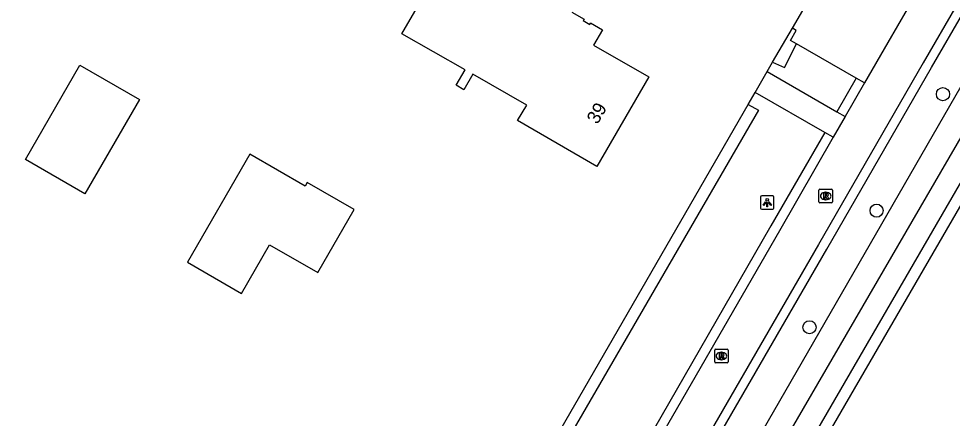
# Model space of a CAD drawing. Extents: x 156502 to 159074, y 384229 to 386094.
# Drawn here: x 157237.7 to 157307.2, y 385687.2 to 385716.9 of the extents above; entities that cross this region are included whole.
import ezdxf

# ---------------------------------------------------------------- set-up
doc = ezdxf.new("R2010")
doc.units = 0
for name, color, linetype in [('IMGEO_Boom', 7, 'Continuous'), ('IMGEO_Gemengd_bos', 7, 'Continuous'), ('IMGEO_Greppel_droge_sloot', 7, 'Continuous'), ('IMGEO_Groenvoorziening', 7, 'Continuous'), ('IMGEO_Hek', 7, 'Continuous'), ('IMGEO_Lichtpunt', 7, 'Continuous'), ('IMGEO_Pand', 7, 'Continuous'), ('IMGEO_Pand_nummerreeks', 7, 'Continuous'), ('IMGEO_Rijbaan_lokaal_halfverhard', 7, 'Continuous'), ('IMGEO_Rijbaan_lokaal_open', 7, 'Continuous'), ('IMGEO_Rioolput', 7, 'Continuous'), ('IMGEO_Voetpad_open', 7, 'Continuous')]:
    doc.layers.add(name, color=color, linetype=linetype)

msp = doc.modelspace()

# ---------------------------------------------------------------- linework, layer by layer
at = {"layer": 'IMGEO_Boom'}
for centre in [(157306.454, 385711.295), (157301.516, 385702.617), (157296.521, 385693.933)]:
    msp.add_circle(centre, 0.489, dxfattribs=at)
at = {"layer": 'IMGEO_Gemengd_bos'}
msp.add_lwpolyline([(157395.472, 385857.325), (157372.587, 385816.736), (157334.959, 385750), (157287.88, 385668.677), (157271.388, 385640.19), (157191.031, 385500), (157152.554, 385432.884), (157150.665, 385429.588), (157146.166, 385421.741)], dxfattribs=at)
at = {"layer": 'IMGEO_Greppel_droge_sloot'}
for points in [[(157393.364, 385858.054), (157393.108, 385857.612), (157362.753, 385804.111), (157325.818, 385739.168), (157293.922, 385684.217), (157277.506, 385655.557), (157259.264, 385623.708), (157238.621, 385587.751), (157224.85, 385563.789), (157203.074, 385525.899), (157174.272, 385475.365), (157161.248, 385452.051), (157151.078, 385433.934), (157146.7, 385427.265), (157144.863, 385424.97)], [(157146.463, 385424.365), (157148.979, 385428.052), (157150.577, 385430.986), (157151.892, 385433.401), (157190.309, 385500.414), (157270.667, 385640.605), (157287.16, 385669.094), (157334.237, 385750.413), (157371.862, 385817.145), (157394.598, 385857.47)]]:
    msp.add_lwpolyline(points, dxfattribs=at)
at = {"layer": 'IMGEO_Groenvoorziening'}
for points in [[(157284.199, 385670.89), (157329.731, 385750), (157392.248, 385858.973)], [(157293.777, 385713.687), (157295.26, 385716.199)], [(157293.777, 385713.687), (157294.665, 385713.269), (157295.56, 385715.032)], [(157293.366, 385712.992), (157293.777, 385713.687)], [(157291.965, 385710.53), (157292.478, 385711.419)], [(157268.668, 385670.142), (157291.965, 385710.53)], [(157291.965, 385710.53), (157292.73, 385710.099), (157269.35, 385669.721)]]:
    msp.add_lwpolyline(points, dxfattribs=at)
at = {"layer": 'IMGEO_Hek'}
msp.add_lwpolyline([(157334.959, 385750), (157287.88, 385668.677)], dxfattribs=at)
at = {"layer": 'IMGEO_Lichtpunt'}
for p, q in [((157292.887, 385703.62), (157292.887, 385702.813)), ((157292.887, 385703.62), (157292.887, 385702.813)), ((157293.789, 385703.715), (157292.981, 385703.715)), ((157293.789, 385703.715), (157292.981, 385703.715)), ((157293.883, 385702.813), (157293.883, 385703.62)), ((157293.883, 385702.813), (157293.883, 385703.62)), ((157292.981, 385702.719), (157293.789, 385702.719)), ((157292.981, 385702.719), (157293.789, 385702.719))]:
    msp.add_line(p, q, dxfattribs=at)
for points in [[(157293.261, 385703.284), (157293.3, 385703.256), (157293.112, 385702.994), (157293.074, 385703.021), (157293.261, 385703.284)], [(157293.363, 385703.236), (157293.41, 385703.236), (157293.41, 385702.914), (157293.363, 385702.914), (157293.363, 385703.236)], [(157293.473, 385703.256), (157293.511, 385703.283), (157293.698, 385703.021), (157293.659, 385702.993), (157293.473, 385703.256)]]:
    msp.add_lwpolyline(points, dxfattribs=at)
msp.add_circle((157293.386, 385703.418), 0.0994, dxfattribs=at)
for centre, start, end in [((157292.981, 385703.62), 90, 180), ((157292.981, 385703.62), 90, 180), ((157293.789, 385703.62), 0, 90), ((157293.789, 385703.62), 0, 90), ((157292.981, 385702.813), 180, 270), ((157292.981, 385702.813), 180, 270), ((157293.789, 385702.813), 270, 0), ((157293.789, 385702.813), 270, 360)]:
    msp.add_arc(centre, 0.0946, start, end, dxfattribs=at)
at = {"layer": 'IMGEO_Pand'}
for points in [[(157278.85, 385717.389), (157279.752, 385716.872), (157279.692, 385716.768), (157280.178, 385716.489), (157280.238, 385716.593), (157281.114, 385716.09), (157280.456, 385714.943), (157284.563, 385712.589), (157280.699, 385705.903), (157274.807, 385709.332), (157275.49, 385710.481), (157271.474, 385712.78), (157270.8, 385711.626), (157270.235, 385711.956), (157270.897, 385713.095), (157266.202, 385715.791), (157267.329, 385717.754)], [(157242.25, 385713.459), (157246.67, 385710.905), (157242.608, 385703.874), (157238.187, 385706.428), (157242.25, 385713.459)], [(157259.94, 385698.001), (157262.648, 385702.694), (157259.152, 385704.71), (157259.002, 385704.451), (157254.891, 385706.823), (157250.249, 385698.779), (157254.274, 385696.456), (157256.358, 385700.067), (157259.94, 385698.001)]]:
    msp.add_lwpolyline(points, dxfattribs=at)
at = {"layer": 'IMGEO_Rijbaan_lokaal_halfverhard'}
for points in [[(157281.966, 385672.234), (157287.901, 385682.571), (157297.811, 385699.744), (157305.606, 385713.266), (157310.603, 385721.93), (157349.521, 385789.087)], [(157299.987, 385712.485), (157298.547, 385709.98)], [(157298.547, 385709.98), (157299.169, 385709.618)], [(157297.663, 385708.443), (157293.657, 385701.479), (157284.326, 385685.265), (157273.57, 385666.582), (157272.301, 385664.385)], [(157298.287, 385708.085), (157297.663, 385708.443)]]:
    msp.add_lwpolyline(points, dxfattribs=at)
at = {"layer": 'IMGEO_Rijbaan_lokaal_open'}
for points in [[(157348.91, 385789.439), (157309.98, 385722.29), (157304.982, 385713.626), (157297.187, 385700.104), (157287.277, 385682.931), (157276.979, 385664.993), (157272.994, 385658.151), (157259.699, 385634.92)], [(157295.26, 385716.199), (157297.594, 385720.232)], [(157303.781, 385717.632), (157302.348, 385715.145), (157300.611, 385712.126)], [(157295.56, 385715.032), (157295.119, 385715.286), (157295.542, 385716.032), (157295.26, 385716.199)], [(157299.987, 385712.485), (157295.56, 385715.032)], [(157300.611, 385712.126), (157299.169, 385709.618)], [(157300.611, 385712.126), (157299.987, 385712.485)], [(157299.169, 385709.618), (157298.287, 385708.085)], [(157298.287, 385708.085), (157294.281, 385701.12), (157284.95, 385684.906), (157274.194, 385666.223), (157272.923, 385664.022)]]:
    msp.add_lwpolyline(points, dxfattribs=at)
at = {"layer": 'IMGEO_Rioolput'}
for p, q in [((157297.231, 385703.283), (157297.231, 385704.135)), ((157297.306, 385704.209), (157298.158, 385704.209)), ((157297.719, 385703.989), (157297.744, 385703.989)), ((157298.232, 385704.135), (157298.232, 385703.283)), ((157298.158, 385703.209), (157297.306, 385703.209)), ((157297.742, 385703.429), (157297.717, 385703.429)), ((157289.47, 385691.37), (157289.47, 385692.222)), ((157289.545, 385692.296), (157290.397, 385692.296)), ((157289.958, 385692.076), (157289.983, 385692.076)), ((157290.471, 385692.222), (157290.471, 385691.37)), ((157290.397, 385691.296), (157289.545, 385691.296)), ((157289.981, 385691.516), (157289.956, 385691.516))]:
    msp.add_line(p, q, dxfattribs=at)
for points in [[(157297.231, 385703.283), (157297.231, 385704.135)], [(157297.306, 385704.209), (157298.158, 385704.209)], [(157297.82, 385703.907), (157297.568, 385703.909), (157297.568, 385703.509)], [(157297.746, 385703.828), (157297.692, 385703.828), (157297.692, 385703.747)], [(157298.232, 385704.135), (157298.232, 385703.283)], [(157298.158, 385703.209), (157297.306, 385703.209)], [(157297.568, 385703.509), (157297.692, 385703.509), (157297.692, 385703.671), (157297.703, 385703.671)], [(157297.692, 385703.747), (157297.744, 385703.747)], [(157297.75, 385703.642), (157297.821, 385703.509), (157297.961, 385703.509), (157297.896, 385703.635)], [(157289.47, 385691.37), (157289.47, 385692.222)], [(157289.545, 385692.296), (157290.397, 385692.296)], [(157290.059, 385691.994), (157289.807, 385691.996), (157289.807, 385691.596)], [(157290.471, 385692.222), (157290.471, 385691.37)], [(157290.397, 385691.296), (157289.545, 385691.296)], [(157289.807, 385691.596), (157289.931, 385691.596), (157289.931, 385691.758), (157289.942, 385691.758)], [(157289.985, 385691.915), (157289.931, 385691.915), (157289.931, 385691.834)], [(157289.931, 385691.834), (157289.983, 385691.834)], [(157289.989, 385691.729), (157290.06, 385691.596), (157290.2, 385691.596), (157290.135, 385691.722)]]:
    msp.add_lwpolyline(points, dxfattribs=at)
for centre, radius, start, end in [((157297.308, 385704.133), 0.0765, 91.55205, 178.44795), ((157297.308, 385704.133), 0.0765, 91.55205, 178.44795), ((157297.752, 385703.732), 0.0964, 77.00612, 93.18647), ((157297.766, 385703.789), 0.0378, 276.66336, 79.67722), ((157297.819, 385703.797), 0.109, 350.36119, 89.41601), ((157297.817, 385703.797), 0.112, 277.58423, 350.98172), ((157298.156, 385704.133), 0.0765, 1.55205, 88.44795), ((157298.156, 385704.133), 0.0765, 1.55205, 88.44795), ((157297.308, 385703.285), 0.0765, 181.55205, 268.44795), ((157297.308, 385703.285), 0.0765, 181.55205, 268.44795), ((157297.702, 385703.618), 0.0533, 26.02933, 88.69889), ((157297.728, 385703.936), 0.19, 274.7715, 282.96867), ((157297.801, 385703.582), 0.108, 29.51342, 73.79051), ((157298.156, 385703.285), 0.0765, 271.55205, 358.44795), ((157298.156, 385703.285), 0.0765, 271.55205, 358.44795), ((157289.547, 385692.22), 0.0765, 91.55205, 178.44795), ((157289.547, 385692.22), 0.0765, 91.55205, 178.44795), ((157290.058, 385691.884), 0.109, 350.36119, 89.41601), ((157290.395, 385692.22), 0.0765, 1.55205, 88.44795), ((157290.395, 385692.22), 0.0765, 1.55205, 88.44795), ((157289.547, 385691.372), 0.0765, 181.55205, 268.44795), ((157289.547, 385691.372), 0.0765, 181.55205, 268.44795), ((157289.941, 385691.705), 0.0533, 26.02933, 88.69889), ((157289.967, 385692.023), 0.19, 274.7715, 282.96867), ((157289.991, 385691.819), 0.0964, 77.00612, 93.18647), ((157290.005, 385691.876), 0.0378, 276.66336, 79.67722), ((157290.056, 385691.884), 0.112, 277.58423, 350.98172), ((157290.04, 385691.669), 0.108, 29.51342, 73.79051), ((157290.395, 385691.372), 0.0765, 271.55205, 358.44795), ((157290.395, 385691.372), 0.0765, 271.55205, 358.44795)]:
    msp.add_arc(centre, radius, start, end, dxfattribs=at)
for centre, major_axis, ratio, start_param, end_param in [((157297.718, 385703.709), (-0.387, 0.002), 0.722429, 4.712389, 7.853982), ((157297.743, 385703.709), (-0.39, 0.002), 0.717154, 1.570796, 4.712389), ((157289.957, 385691.796), (-0.387, 0.002), 0.722429, 4.712389, 7.853982), ((157289.982, 385691.796), (-0.39, 0.002), 0.717154, 1.570796, 4.712389)]:
    msp.add_ellipse(centre, major_axis=major_axis, ratio=ratio, start_param=start_param, end_param=end_param, dxfattribs=at)
at = {"layer": 'IMGEO_Voetpad_open'}
for points in [[(157292.478, 385711.419), (157293.366, 385712.992)], [(157293.366, 385712.992), (157298.547, 385709.98)], [(157297.663, 385708.443), (157292.478, 385711.419)]]:
    msp.add_lwpolyline(points, dxfattribs=at)

# ---------------------------------------------------------------- texts
at = {"layer": 'IMGEO_Pand_nummerreeks'}
msp.add_text('39', height=1, rotation=59.97722, dxfattribs=at).set_placement((157280.752, 385708.991))

doc.saveas('drawing.dxf')
